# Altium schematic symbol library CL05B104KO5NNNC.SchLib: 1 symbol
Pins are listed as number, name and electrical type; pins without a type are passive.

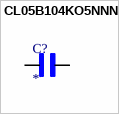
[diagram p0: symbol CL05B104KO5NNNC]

## CL05B104KO5NNNC
designator C?
0.1 ÂµF Â±10% 16V Ceramic Capacitor X7R 0402 (1005 Metric); MF: Samsung; MP: CL05B104KO5NNNC
footprint CAPC1005X55N
pins: 1, 2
